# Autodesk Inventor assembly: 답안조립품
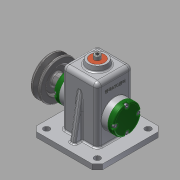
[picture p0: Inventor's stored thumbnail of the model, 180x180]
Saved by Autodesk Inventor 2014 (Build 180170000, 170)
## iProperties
Created: 2016-02
Part Number: 답안조립품
Document SubType Name: Assembly
Designer: USER
Author: USER
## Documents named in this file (16)
- C:\Users\USER\Desktop\460211V1009\답안조립품.iam
- C:\Users\USER\Desktop\460211V1009\V벨트풀리.ipt
- C:\Users\USER\Desktop\460211V1009\고정핀 1.2 x 10.ipt
- C:\Users\USER\Desktop\460211V1009\뒤커버.ipt
- C:\Users\USER\Desktop\460211V1009\링크.ipt
- C:\Users\USER\Desktop\460211V1009\멈춤나사 M3x8.ipt
- C:\Users\USER\Desktop\460211V1009\베어링 12 x 32 x 10.ipt
- C:\Users\USER\Desktop\460211V1009\본체.ipt
- C:\Users\USER\Desktop\460211V1009\볼트 M4 x 12.ipt
- C:\Users\USER\Desktop\460211V1009\부시.ipt
- C:\Users\USER\Desktop\460211V1009\슬라이드.ipt
- C:\Users\USER\Desktop\460211V1009\앞커버.ipt
- C:\Users\USER\Desktop\460211V1009\오일실 12 25 7.ipt
- C:\Users\USER\Desktop\460211V1009\키 4 x 4 x 10.ipt
- C:\Users\USER\Desktop\460211V1009\편심축.ipt
- C:\Users\USER\Desktop\460211V1009\핀 5 x 18.ipt
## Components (11 placed, 4 different names)
1. V벨트풀리:1
2. 핀 5 x 18:1
3. 고정핀 1.2 x 10:2
4. ISO 4762 M4 x 12:1
5. ISO 4762 M4 x 12:2
6. ISO 4762 M4 x 12:3
7. ISO 4762 M4 x 12:4
8. ISO 4762 M4 x 12:5
9. ISO 4762 M4 x 12:6
10. ISO 4762 M4 x 12:7
11. ISO 4762 M4 x 12:8
